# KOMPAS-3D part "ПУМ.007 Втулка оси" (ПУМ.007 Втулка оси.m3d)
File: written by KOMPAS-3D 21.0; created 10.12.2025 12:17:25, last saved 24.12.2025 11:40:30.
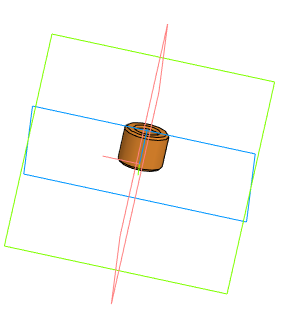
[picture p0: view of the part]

Document properties: Автор: User; Полное имя файла: C:\Users\User\Desktop\ПУ\ПУМ\ПУМ.007 Втулка оси.m3d

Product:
- Part/product: ПУМ.007 Втулка оси
    Масса: 0.003508

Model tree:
1. Эскиз:1
2. Элемент выдавливания:1
     Расстояние 1 = 8
3. Фаска:1  (with: Элемент выдавливания:1)
     Угол = 45; Длина 1 = 0.5; Длина 2 = 0.5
